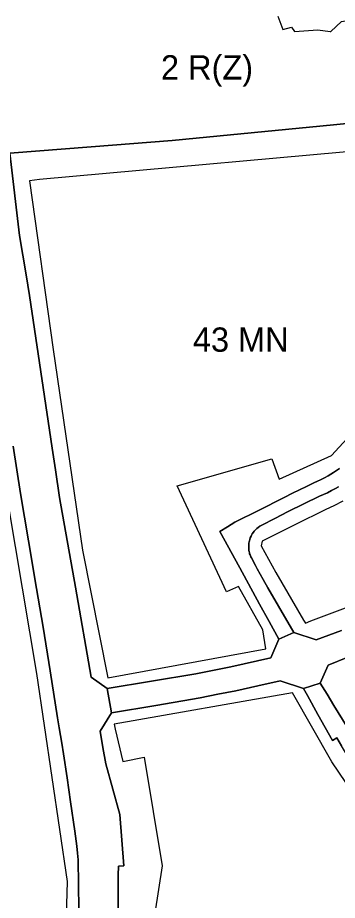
# Model space of a CAD drawing. Extents: x 7423432 to 7425824, y 5537848 to 5539677.
# Drawn here: x 7424289.1 to 7424420.7, y 5539125.1 to 5539488.4 of the extents above; entities that cross this region are included whole.
import ezdxf

# ---------------------------------------------------------------- set-up
doc = ezdxf.new("R2010")
doc.units = 0
for name, color, linetype in [('linie_rozgraniczajace', 7, 'Continuous'), ('linie_zabudowy_nieprzekraczalne', 7, 'Continuous'), ('oznaczenia_przeznaczen', 7, 'Continuous')]:
    doc.layers.add(name, color=color, linetype=linetype)

msp = doc.modelspace()

# ---------------------------------------------------------------- linework, layer by layer
at = {"layer": 'linie_rozgraniczajace'}
for points in [[(7424477.08, 5539490.55), (7424481.18, 5539481.82), (7424482.56, 5539478.9), (7424484.89, 5539473.48), (7424486.96, 5539468.52), (7424486.12, 5539459.68), (7424485.29, 5539450.85), (7424419.02, 5539444.34), (7424352.75, 5539437.84), (7424319.32, 5539435.23), (7424285.89, 5539432.62)], [(7424396.14, 5539489.1), (7424398.27, 5539483.53), (7424401.86, 5539484.56), (7424403.06, 5539482.79), (7424412.69, 5539483.41), (7424417.64, 5539482.77), (7424417.94, 5539482.73), (7424422.37, 5539486.9), (7424445.03, 5539490.67)], [(7424421.51, 5539302.86), (7424420.32, 5539302.05), (7424419.14, 5539301.25), (7424418.01, 5539300.58), (7424416.87, 5539299.92), (7424415.33, 5539299.1), (7424413.78, 5539298.28), (7424412.43, 5539297.64), (7424411, 5539296.97), (7424409.66, 5539296.31), (7424408.31, 5539295.65), (7424404.77, 5539293.92), (7424402.47, 5539292.8), (7424398.46, 5539290.84), (7424388.5, 5539285.79), (7424378.54, 5539280.73), (7424375.44, 5539278.84), (7424372.34, 5539276.95), (7424380.49, 5539262), (7424388.65, 5539247.05), (7424392.65, 5539239.87), (7424396.65, 5539232.69), (7424393.32, 5539224.95), (7424376.77, 5539221.2), (7424362.46, 5539218.38), (7424344.22, 5539215.37), (7424325.97, 5539212.34), (7424319.36, 5539217.03), (7424312.88, 5539253.98), (7424306.41, 5539290.93), (7424304.68, 5539302.27), (7424303.32, 5539311.24), (7424302.22, 5539318.68), (7424298.14, 5539346.4), (7424294.07, 5539374.12), (7424292.6, 5539382.59), (7424291.26, 5539390.66), (7424289.93, 5539398.75), (7424285.89, 5539432.62), (7424319.32, 5539435.23), (7424352.75, 5539437.84), (7424419.02, 5539444.34), (7424485.29, 5539450.85)], [(7424285.89, 5539432.62), (7424289.93, 5539398.75), (7424291.26, 5539390.66), (7424292.6, 5539382.59), (7424294.07, 5539374.12), (7424298.14, 5539346.4), (7424302.22, 5539318.68), (7424303.32, 5539311.24), (7424304.68, 5539302.27), (7424306.41, 5539290.93), (7424312.88, 5539253.98), (7424319.36, 5539217.03), (7424325.97, 5539212.34), (7424327.76, 5539202.25), (7424323.12, 5539194.79), (7424324.24, 5539188.08), (7424325.36, 5539181.36), (7424328.27, 5539170.92), (7424331.18, 5539160.47), (7424331.99, 5539149.9), (7424332.81, 5539139.33), (7424330.65, 5539139.19), (7424330.51, 5539135.48)], [(7424287.26, 5539312.04), (7424290.24, 5539292.63), (7424293.57, 5539273.07), (7424296.9, 5539253.51), (7424299.58, 5539237.59), (7424302.46, 5539219.66), (7424305.58, 5539200.31), (7424306.24, 5539196.18), (7424307.32, 5539189.77), (7424308.05, 5539185.44), (7424309.48, 5539175.58), (7424310.92, 5539165.72), (7424312.64, 5539153.65), (7424313.46, 5539147.41), (7424313.76, 5539144.58), (7424314.05, 5539141.76), (7424314.28, 5539121.55), (7424314.5, 5539101.35), (7424288.25, 5539099.74)], [(7424314.28, 5539121.55), (7424314.05, 5539141.76), (7424313.76, 5539144.58), (7424313.46, 5539147.41), (7424312.64, 5539153.65), (7424310.92, 5539165.72), (7424309.48, 5539175.58), (7424308.05, 5539185.44), (7424307.32, 5539189.77), (7424306.24, 5539196.18), (7424305.58, 5539200.31), (7424302.46, 5539219.66), (7424299.58, 5539237.59), (7424296.9, 5539253.51), (7424293.57, 5539273.07), (7424290.24, 5539292.63), (7424287.26, 5539312.04)], [(7424372.34, 5539276.95), (7424375.44, 5539278.84), (7424378.54, 5539280.73), (7424388.5, 5539285.79), (7424398.46, 5539290.84), (7424402.47, 5539292.8), (7424404.77, 5539293.92), (7424408.31, 5539295.65), (7424409.66, 5539296.31), (7424411, 5539296.97), (7424412.43, 5539297.64), (7424413.78, 5539298.28), (7424415.33, 5539299.1), (7424416.87, 5539299.92), (7424418.01, 5539300.58), (7424419.14, 5539301.25), (7424420.32, 5539302.05), (7424421.51, 5539302.86)], [(7424419.96, 5539294.67), (7424418.25, 5539293.79), (7424416.55, 5539292.92), (7424414.93, 5539292.18), (7424413.32, 5539291.44), (7424406.89, 5539288.28), (7424400.46, 5539285.13), (7424394.99, 5539282.35), (7424389.53, 5539279.58), (7424388.76, 5539279.12), (7424388.09, 5539278.64), (7424387.59, 5539278.23), (7424387.2, 5539277.86), (7424386.83, 5539277.48), (7424386.45, 5539277.04), (7424386.13, 5539276.62), (7424385.68, 5539275.94), (7424385.4, 5539275.47), (7424385.15, 5539274.97), (7424384.86, 5539274.29), (7424384.63, 5539273.61), (7424384.49, 5539273.13), (7424384.4, 5539272.73), (7424384.29, 5539272.12), (7424384.22, 5539271.49), (7424384.19, 5539270.79), (7424384.2, 5539270.19), (7424384.23, 5539269.66), (7424384.31, 5539269.09), (7424384.38, 5539268.67), (7424384.47, 5539268.23), (7424384.56, 5539267.78), (7424384.73, 5539267.3), (7424384.89, 5539266.87), (7424385.06, 5539266.5), (7424385.28, 5539266.06), (7424386.94, 5539262.98), (7424387.68, 5539261.61), (7424390.09, 5539257.16), (7424392.04, 5539253.8), (7424396.42, 5539246.28), (7424402.76, 5539235.4), (7424396.65, 5539232.69), (7424392.65, 5539239.87), (7424388.65, 5539247.05), (7424380.49, 5539262), (7424372.34, 5539276.95)], [(7424422.43, 5539236.19), (7424411.9, 5539232.41), (7424402.76, 5539235.4), (7424396.42, 5539246.28), (7424392.04, 5539253.8), (7424390.09, 5539257.16), (7424387.68, 5539261.61), (7424386.94, 5539262.98), (7424385.28, 5539266.06), (7424385.06, 5539266.5), (7424384.89, 5539266.87), (7424384.73, 5539267.3), (7424384.56, 5539267.78), (7424384.47, 5539268.23), (7424384.38, 5539268.67), (7424384.31, 5539269.09), (7424384.23, 5539269.66), (7424384.2, 5539270.19), (7424384.19, 5539270.79), (7424384.22, 5539271.49), (7424384.29, 5539272.12), (7424384.4, 5539272.73), (7424384.49, 5539273.13), (7424384.63, 5539273.61), (7424384.86, 5539274.29), (7424385.15, 5539274.97), (7424385.4, 5539275.47), (7424385.68, 5539275.94), (7424386.13, 5539276.62), (7424386.45, 5539277.04), (7424386.83, 5539277.48), (7424387.2, 5539277.86), (7424387.59, 5539278.23), (7424388.09, 5539278.64), (7424388.76, 5539279.12), (7424389.53, 5539279.58), (7424394.99, 5539282.35), (7424400.46, 5539285.13), (7424406.89, 5539288.28), (7424413.32, 5539291.44), (7424414.93, 5539292.18), (7424416.55, 5539292.92), (7424418.25, 5539293.79), (7424419.96, 5539294.67), (7424421.14, 5539295.37)], [(7424421.14, 5539295.37), (7424419.96, 5539294.67)], [(7424325.97, 5539212.34), (7424344.22, 5539215.37), (7424362.46, 5539218.38), (7424376.77, 5539221.2), (7424393.32, 5539224.95), (7424396.65, 5539232.69), (7424402.76, 5539235.4), (7424411.9, 5539232.41), (7424422.43, 5539236.19)], [(7424424.93, 5539225.23), (7424416.82, 5539221.95), (7424413.66, 5539214.52), (7424406.7, 5539212.34), (7424397.1, 5539215.55), (7424387.97, 5539213.48), (7424378.84, 5539211.42), (7424371.54, 5539209.98), (7424364.25, 5539208.54), (7424346, 5539205.4), (7424327.76, 5539202.25), (7424325.97, 5539212.34)], [(7424424.59, 5539196.66), (7424419.28, 5539205.37), (7424416.47, 5539209.95), (7424413.66, 5539214.52), (7424416.82, 5539221.95), (7424424.93, 5539225.23)], [(7424330.44, 5539121.77), (7424330.51, 5539135.48), (7424330.65, 5539139.19), (7424332.81, 5539139.33), (7424331.99, 5539149.9), (7424331.18, 5539160.47), (7424328.27, 5539170.92), (7424325.36, 5539181.36), (7424324.24, 5539188.08), (7424323.12, 5539194.79), (7424327.76, 5539202.25), (7424346, 5539205.4), (7424364.25, 5539208.54), (7424371.54, 5539209.98), (7424378.84, 5539211.42), (7424387.97, 5539213.48), (7424397.1, 5539215.55), (7424406.7, 5539212.34), (7424408.34, 5539209.39), (7424412.67, 5539201.63), (7424418.64, 5539190.92), (7424420.41, 5539191.98), (7424422.39, 5539188.75)], [(7424406.7, 5539212.34), (7424413.66, 5539214.52), (7424416.47, 5539209.95), (7424419.28, 5539205.37), (7424424.59, 5539196.66)], [(7424428.03, 5539179.36), (7424424.08, 5539186.01), (7424422.39, 5539188.75), (7424420.41, 5539191.98), (7424418.64, 5539190.92), (7424412.67, 5539201.63), (7424408.34, 5539209.39), (7424406.7, 5539212.34)], [(7424330.51, 5539135.48), (7424330.44, 5539121.77)]]:
    msp.add_lwpolyline(points, dxfattribs=at)
at = {"layer": 'linie_zabudowy_nieprzekraczalne'}
for points in [[(7424464.09, 5539436.39), (7424463.29, 5539396.95), (7424450.52, 5539435.6), (7424298.13, 5539421.81), (7424293.96, 5539421.24), (7424303.75, 5539351.91), (7424315.76, 5539269.24), (7424326.17, 5539216.7), (7424391.29, 5539228.61), (7424389.98, 5539236.5), (7424379.98, 5539254.3), (7424375.1, 5539252.12), (7424354.77, 5539295.74), (7424393.75, 5539306.92), (7424396.74, 5539298.44), (7424418.21, 5539308.25), (7424426.15, 5539316.84), (7424465.06, 5539359.62), (7424499.41, 5539380.44), (7424504.14, 5539433.99), (7424464.09, 5539436.39)], [(7424272.25, 5539057.3), (7424269.66, 5539046.74), (7424276.81, 5539019.63), (7424286.43, 5539017.31), (7424299.87, 5539051.45), (7424304.2, 5539064.48), (7424306.06, 5539072.43), (7424308.31, 5539085.76), (7424309.6, 5539132.87), (7424297.04, 5539218.5), (7424282.3, 5539305.84), (7424276.47, 5539305.07), (7424267.67, 5539364.7), (7424261.54, 5539410.77)], [(7424422.86, 5539289.42), (7424419.17, 5539287.52), (7424415.89, 5539286.02), (7424403.14, 5539279.76), (7424389.73, 5539272.95), (7424389.26, 5539271.07), (7424395.31, 5539260.12), (7424406.79, 5539240.39), (7424407.51, 5539239.27), (7424409.7, 5539240.15), (7424537.69, 5539288.2)], [(7424427.01, 5539169.33), (7424418.37, 5539182.22), (7424418.37, 5539182.22), (7424418.37, 5539182.22), (7424402.22, 5539210.52), (7424402.22, 5539210.52), (7424328.84, 5539197.69), (7424329.18, 5539195.66), (7424332.46, 5539182.35), (7424341.16, 5539184.11), (7424348.6, 5539139.34), (7424348.6, 5539139.34), (7424337.54, 5539067.6)]]:
    msp.add_lwpolyline(points, dxfattribs=at)

# ---------------------------------------------------------------- texts
at = {"layer": 'oznaczenia_przeznaczen'}
for s, p in [('2 R(Z)', (7424348.11, 5539462.97)), ('43 MN', (7424361.23, 5539350.92))]:
    msp.add_text(s, height=10, dxfattribs=at).set_placement(p)

doc.saveas('drawing.dxf')
